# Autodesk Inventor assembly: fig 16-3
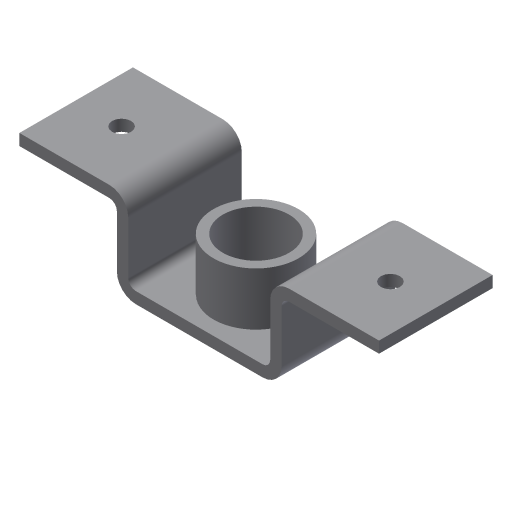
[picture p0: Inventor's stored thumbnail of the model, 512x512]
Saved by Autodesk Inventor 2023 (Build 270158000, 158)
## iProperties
Created: 2004-07
Part Number: fig 16-3
Document SubType Name: Weldment
Designer: CADCIM Technologies
Manufacturer: Standard
Standards Organization: Custom
Author: CADCIM Technologies
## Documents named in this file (3)
- D:\PROJECTS\Project 2022\Autodesk Inventor For Professional 2023\RESOURCES INVENTOR 2023\RESOURCES INVENTOR 2023\Inventor_2023_Part\Inventor_2023_Part\c16_Inv_2023_prt\fig 16-3.iam
- D:\PROJECTS\Project 2022\Autodesk Inventor For Professional 2023\RESOURCES INVENTOR 2023\RESOURCES INVENTOR 2023\Inventor_2023_Part\Inventor_2023_Part\c16_Inv_2023_prt\Bracket.ipt
- D:\PROJECTS\Project 2022\Autodesk Inventor For Professional 2023\RESOURCES INVENTOR 2023\RESOURCES INVENTOR 2023\Inventor_2023_Part\Inventor_2023_Part\c16_Inv_2023_prt\cylinder.ipt
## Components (2 placed, 2 different names)
1. Bracket:1 — Insert:1
2. cylinder:1 — Insert:1
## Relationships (1: Insert 1)
- Insert:1: Bracket:1 ↔ cylinder:1
